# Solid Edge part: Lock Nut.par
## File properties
Author: Sarvanan
Template: sync iso part.par
Last saved by: CADCIM
Revision: 6
Application: Solid Edge
Accuracy: 0.990
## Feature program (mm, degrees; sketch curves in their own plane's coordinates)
sketch for "Hole_1" plane through (21.0838, 43.6973, 8) normal (0, 0, 1) x-axis (1, 0, 0)
  hole centre (-1.3414, 0.2221) bore radius 6
hole "Hole_1" diameter 12 through
pattern "unnamed Pattern 1" of "Hole_1"
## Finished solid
Body 1: solid body, 21 faces, 56 edges, 36 vertices.
  Faces by surface: spun 12, plane 8, cylinder 1
  Edges by curve: circle 21, line 18, intersection 17
Bounding box of the edges (mm; curved faces can reach further): 30.022 x 26.000 x 8.000, from (4.7313, 30.9194, 0) to (34.7535, 56.9194, 8).
Cylindrical faces by radius (mm): R6 x1
Planar faces by outward normal: +y 1, +z 1, -y 1, -z 1, oblique 4
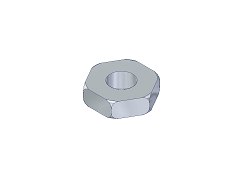
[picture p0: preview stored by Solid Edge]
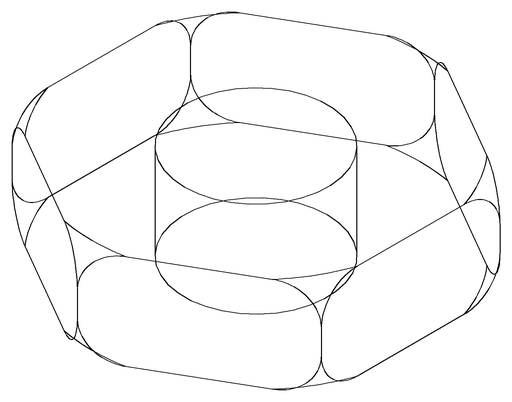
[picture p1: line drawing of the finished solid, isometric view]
